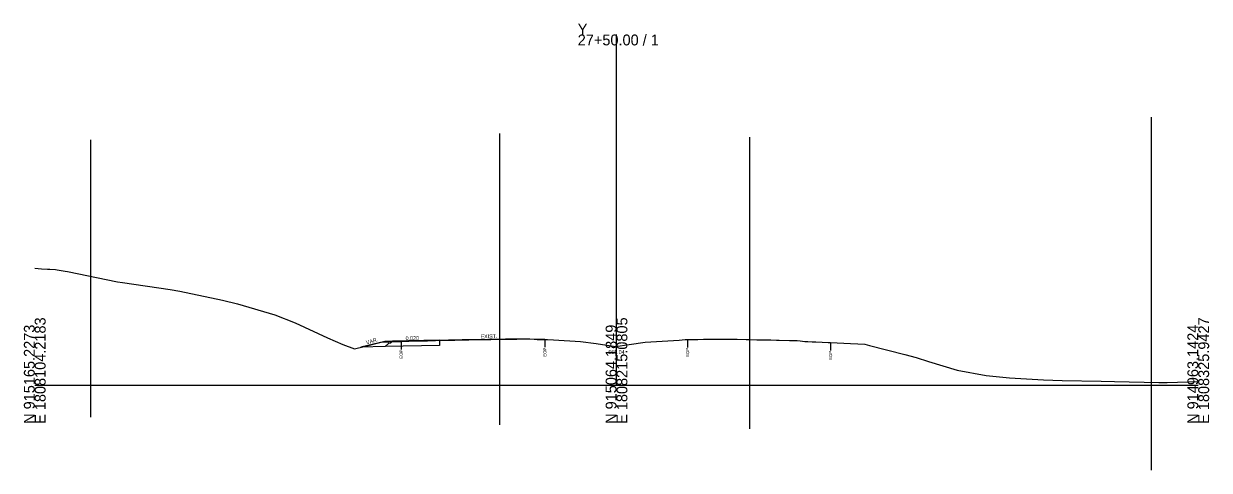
# Model space of a CAD drawing. Extents: x -26 to 3303, y -30 to 9580.
# Drawn here: x 997.2 to 1302.8, y 7478 to 7593.3 of the extents above; entities that cross this region are included whole.
import ezdxf

# ---------------------------------------------------------------- set-up
doc = ezdxf.new("R2010")
doc.units = 0
for name, color, linetype in [('Exist Cross Section Cell', 7, 'Continuous'), ('Exist XS Center Line Elevation Label', 7, 'Continuous'), ('Exist XS Ground Line', 7, 'Continuous'), ('Old_Level_10', 7, 'Continuous'), ('Prop XS Ditch Slope Text', 7, 'Continuous'), ('Prop XS Earthwork Shape', 7, 'Continuous'), ('Prop XS Exc Vertical Line 1', 7, 'Continuous'), ('Prop XS Exc Vertical Line 2', 7, 'Continuous'), ('Prop XS Exc Vertical Line 3', 7, 'Continuous'), ('Prop XS Exc Vertical Line 4', 7, 'Continuous'), ('Prop XS Finish Grade', 7, 'Continuous'), ('Prop XS Finish Grade Paved Shoulder', 7, 'Continuous'), ('Prop XS Pvmt Edge Slope', 7, 'Continuous'), ('Prop XS SE Text', 7, 'Continuous'), ('Prop XS Subgrade', 7, 'Continuous'), ('Prop XS Subgrade Earthwork', 7, 'Continuous')]:
    doc.layers.add(name, color=color, linetype=linetype)

msp = doc.modelspace()

# ---------------------------------------------------------------- linework, layer by layer
at = {"layer": 'Exist Cross Section Cell'}
for p, q in [((1150, 7500), (1150, 7590.51)), ((1000, 7500), (1150, 7500)), ((1150, 7500), (1300, 7500))]:
    msp.add_line(p, q, dxfattribs=at)
at = {"layer": 'Exist XS Ground Line'}
msp.add_lwpolyline([(1000, 7530.17), (1001.73, 7530.06), (1003.27, 7529.96), (1003.9, 7529.92), (1005.39, 7529.83), (1005.77, 7529.74), (1007.82, 7529.45), (1008.47, 7529.32), (1021.35, 7526.67), (1022.61, 7526.47), (1034.88, 7524.67), (1037.45, 7524.23), (1048.41, 7521.9), (1052.3, 7520.96), (1061.94, 7518.16), (1067.14, 7516.08), (1075.47, 7512.24), (1079.4, 7510.46), (1082.41, 7509.41), (1084.9, 7510.01), (1089.32, 7511.06), (1093.27, 7511.23), (1094.45, 7511.28), (1095.15, 7511.31), (1096.47, 7511.34), (1099.07, 7511.4), (1099.91, 7511.41), (1101.29, 7511.46), (1102.77, 7511.5), (1103.33, 7511.53), (1104.35, 7511.64), (1106.67, 7511.67), (1108.35, 7511.7), (1110.23, 7511.74), (1111.89, 7511.76), (1113.95, 7511.79), (1115.31, 7511.81), (1115.79, 7511.82), (1117.21, 7511.84), (1117.64, 7511.85), (1120.15, 7511.88), (1120.74, 7511.89), (1121.39, 7511.89), (1122.51, 7511.9), (1123.57, 7511.91), (1124.27, 7511.91), (1125.03, 7511.92), (1126.04, 7511.92), (1126.62, 7511.93), (1127.65, 7511.94), (1128.77, 7511.88), (1129.59, 7511.82), (1130.23, 7511.81), (1131.53, 7511.81), (1132.18, 7511.77), (1133.73, 7511.69), (1140.71, 7511.29), (1144.72, 7510.72), (1149.77, 7510.01), (1153.24, 7510.52), (1157.39, 7511.1), (1166.12, 7511.64), (1167.73, 7511.74), (1168.34, 7511.77), (1169.39, 7511.77), (1170.29, 7511.76), (1170.94, 7511.8), (1172.39, 7511.9), (1173.58, 7511.89), (1174.27, 7511.88), (1175.58, 7511.87), (1177.03, 7511.86), (1177.37, 7511.86), (1177.68, 7511.86), (1180.75, 7511.84), (1181.07, 7511.83), (1183.47, 7511.81), (1184.09, 7511.79), (1184.44, 7511.79), (1186.2, 7511.73), (1188.17, 7511.7), (1189.76, 7511.67), (1191.22, 7511.64), (1191.91, 7511.62), (1194.64, 7511.56), (1195.86, 7511.51), (1196.59, 7511.49), (1197.37, 7511.4), (1197.95, 7511.34), (1198.6, 7511.28), (1199.32, 7511.25), (1200.41, 7511.2), (1201.4, 7511.17), (1202.99, 7511.1), (1204.56, 7511.03), (1205.21, 7511), (1210.37, 7510.74), (1212.18, 7510.65), (1214.01, 7510.55), (1215.27, 7510.25), (1224.31, 7507.91), (1227.23, 7507.16), (1230.44, 7506.07), (1237.84, 7503.87), (1245.28, 7502.53), (1251.37, 7501.86), (1260.13, 7501.35), (1264.9, 7501.21), (1274.97, 7501.02), (1278.43, 7500.97), (1289.82, 7500.68), (1291.96, 7500.69), (1300, 7500.94)], dxfattribs=at)
at = {"layer": 'Old_Level_10'}
for p, q in [((1094.45, 7511.28), (1094.45, 7509.23)), ((1131.53, 7511.81), (1131.53, 7509.76)), ((1168.34, 7511.77), (1168.34, 7509.72)), ((1205.21, 7511), (1205.21, 7508.95))]:
    msp.add_line(p, q, dxfattribs=at)
at = {"layer": 'Prop XS Earthwork Shape'}
for points in [[(1096.47, 7511.34), (1099.07, 7511.4), (1099.91, 7511.41), (1101.29, 7511.46), (1102.77, 7511.5), (1103.33, 7511.53), (1104.35, 7511.64), (1104.35, 7510.22), (1090.34, 7509.94), (1084.09, 7509.81), (1084.9, 7510.01), (1089.32, 7511.06), (1093.27, 7511.23), (1094.45, 7511.28), (1095.15, 7511.31)], [(1099.07, 7511.4), (1099.91, 7511.41), (1101.29, 7511.46), (1102.77, 7511.5), (1103.33, 7511.53), (1104.35, 7511.64), (1104.35, 7510.22), (1090.34, 7509.94), (1084.09, 7509.81), (1084.9, 7510.01), (1089.32, 7511.06), (1093.27, 7511.23), (1094.45, 7511.28), (1095.15, 7511.31), (1096.47, 7511.34)]]:
    msp.add_lwpolyline(points, close=True, dxfattribs=at)
at = {"layer": 'Prop XS Exc Vertical Line 1'}
msp.add_line((1014.5, 7491.69), (1014.5, 7563.34), dxfattribs=at)
at = {"layer": 'Prop XS Exc Vertical Line 2'}
msp.add_line((1119.95, 7489.74), (1119.95, 7564.97), dxfattribs=at)
at = {"layer": 'Prop XS Exc Vertical Line 3'}
msp.add_line((1184.4, 7488.76), (1184.4, 7564), dxfattribs=at)
at = {"layer": 'Prop XS Exc Vertical Line 4'}
msp.add_line((1287.9, 7478.01), (1287.9, 7569.21), dxfattribs=at)
at = {"layer": 'Prop XS Finish Grade'}
for p, q in [((1090.29, 7511.23), (1084.09, 7509.81)), ((1092.29, 7511.39), (1090.29, 7511.23))]:
    msp.add_line(p, q, dxfattribs=at)
at = {"layer": 'Prop XS Finish Grade Paved Shoulder'}
msp.add_line((1104.35, 7511.64), (1092.29, 7511.39), dxfattribs=at)
at = {"layer": 'Prop XS Pvmt Edge Slope'}
for p, q in [((1090.34, 7509.94), (1091.19, 7510.79)), ((1091.69, 7510.8), (1091.19, 7510.79)), ((1092.29, 7511.39), (1091.69, 7510.8))]:
    msp.add_line(p, q, dxfattribs=at)
at = {"layer": 'Prop XS Subgrade'}
for p, q in [((1104.35, 7511.58), (1106.67, 7511.62)), ((1106.67, 7511.62), (1108.35, 7511.65)), ((1108.35, 7511.65), (1110.23, 7511.68)), ((1110.23, 7511.68), (1111.89, 7511.7)), ((1111.89, 7511.7), (1113.95, 7511.74)), ((1123.57, 7511.85), (1121.39, 7511.84)), ((1124.27, 7511.86), (1123.57, 7511.85)), ((1125.03, 7511.86), (1124.27, 7511.86)), ((1126.04, 7511.87), (1125.03, 7511.86)), ((1126.62, 7511.88), (1126.04, 7511.87)), ((1127.65, 7511.89), (1126.62, 7511.88)), ((1128.77, 7511.82), (1127.65, 7511.89)), ((1129.58, 7511.77), (1128.77, 7511.82)), ((1130.23, 7511.76), (1129.59, 7511.77)), ((1131.53, 7511.75), (1130.23, 7511.76))]:
    msp.add_line(p, q, dxfattribs=at)
for points in [[(1104.35, 7511.64), (1106.67, 7511.67), (1108.35, 7511.7), (1110.23, 7511.74), (1111.89, 7511.76), (1113.95, 7511.79), (1115.31, 7511.81), (1115.79, 7511.82), (1117.21, 7511.84), (1117.64, 7511.85), (1120.15, 7511.88), (1120.74, 7511.89), (1121.39, 7511.89), (1122.51, 7511.9), (1123.57, 7511.91), (1124.27, 7511.91), (1125.03, 7511.92), (1126.04, 7511.92), (1126.62, 7511.93), (1127.65, 7511.94), (1128.77, 7511.88), (1129.59, 7511.82), (1130.23, 7511.81), (1131.53, 7511.81)], [(1113.95, 7511.74), (1115.31, 7511.76), (1115.79, 7511.76)], [(1115.79, 7511.76), (1117.21, 7511.79), (1117.64, 7511.8)], [(1117.64, 7511.8), (1120.15, 7511.83), (1120.74, 7511.83), (1121.39, 7511.84)]]:
    msp.add_lwpolyline(points, dxfattribs=at)
for centre, start, end in [((1106.67, 7511.67), 270.8803, 271.1302), ((1111.89, 7511.76), 270.6896, 270.8979), ((1115.79, 7511.82), 270.8679, 271.0894), ((1117.64, 7511.85), 270.6878, 270.7074), ((1124.27, 7511.91), 270.332, 270.4303), ((1126.04, 7511.92), 270.3325, 270.6568), ((1126.62, 7511.93), 270.6568, 270.7106), ((1129.59, 7511.82), 266.0068, 269.4551), ((1130.23, 7511.81), 269.4551, 269.6673)]:
    msp.add_arc(centre, 0.052, start, end, dxfattribs=at)
at = {"layer": 'Prop XS Subgrade Earthwork'}
for p, q in [((1104.35, 7511.64), (1104.35, 7510.22)), ((1090.34, 7509.94), (1084.09, 7509.81)), ((1104.35, 7510.22), (1090.34, 7509.94))]:
    msp.add_line(p, q, dxfattribs=at)

# ---------------------------------------------------------------- texts
at = {"layer": 'Exist Cross Section Cell'}
for s, p in [('Y', (1140, 7590.51)), ('27+50.00 / 1', (1140, 7587.71))]:
    msp.add_text(s, height=2.8, dxfattribs=at).set_placement(p)
for s, p in [('E 1808104.2183', (1002.8, 7490)), ('E 1808215.0805', (1152.8, 7490)), ('E 1808325.9427', (1302.8, 7490)), ('N 915165.2273', (1000, 7490)), ('N 915064.1849', (1150, 7490)), ('N 914963.1424', (1300, 7490))]:
    msp.add_text(s, height=2.8, rotation=90, dxfattribs=at).set_placement(p)
at = {"layer": 'Exist XS Center Line Elevation Label'}
msp.add_text('668.04', height=1, dxfattribs=at).set_placement((1147.86, 7508.04))
at = {"layer": 'Old_Level_10'}
for p in [(1094.85, 7506.84), (1131.92, 7507.36), (1168.73, 7507.33), (1205.6, 7506.56)]:
    msp.add_text('EOP', height=0.787, rotation=90, dxfattribs=at).set_placement(p)
at = {"layer": 'Prop XS Ditch Slope Text'}
msp.add_text('VAR.', height=1, rotation=15.3069, dxfattribs=at).set_placement((1085.55, 7510.49))
at = {"layer": 'Prop XS SE Text'}
for s, p in [('0.020', (1095.63, 7511.6)), ('EXIST.', (1114.94, 7512.06))]:
    msp.add_text(s, height=1, rotation=1.1458, dxfattribs=at).set_placement(p)

doc.saveas('drawing.dxf')
